(* Logix 5000 project; controller Example_PLC vendor 1 type 14 code 77 rev 19.11; software revision 19.01; part 2 of 6 *)
(* tags used below, declared in another part *)
   Attribute_Number : INT;   // Attribute Number (see help for options)
   ENABLE : BOOL;
   from : BOOL;
(* AKD_Get_Attribute, continued *)

ROUTINE Prescan   (* ladder *)
// Prescan
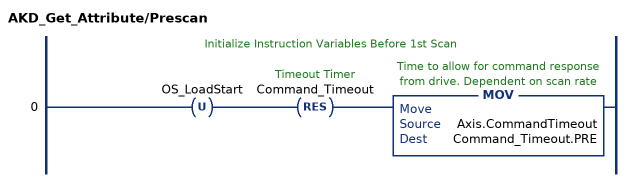
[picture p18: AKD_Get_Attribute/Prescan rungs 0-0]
   // Initialize Instruction Variables Before 1st Scan
   0: OTU(OS_LoadStart)RES(Command_Timeout)MOV(Axis.CommandTimeout,Command_Timeout.PRE);
END_ROUTINE
END_ADD_ON_INSTRUCTION

ADD_ON_INSTRUCTION AKD_Get_Parameter   (* revision 2.0, ExecutePrescan, ExecuteEnableInFalse *)
// Get Drive Parameter
VAR_OUTPUT
   DN : BOOL; {access Read Only, visible}   // Command Successful
   ER : BOOL; {access Read Only, visible}   // Error
END_VAR
VAR_IN_OUT
   Axis : AKD_Axis; {required}
END_VAR
VAR_INPUT
   Parameter_Number : INT; {visible}   // See help (F1) for parameter list.
END_VAR
VAR_OUTPUT
   Parameter_Value : DINT; {access Read Only, required}   // Parameter Value
END_VAR
VAR
   Command_Timeout : TIMER := (PRE := 2000);   // Timeout Timer
   Command_Message_Type : SINT;   // Command Message Type
   Command_Axis_Number : SINT;   // Command Axis Number
   Step : SINT;
   Command_Bytes : SINT[8];
   OS_LoadStart : BOOL;
   Temp_Bytes : SINT[2];   // Temporary Bytes to Split into Command Bytes
END_VAR

ROUTINE EnableInFalse   (* ladder *)
// EnableIn_False
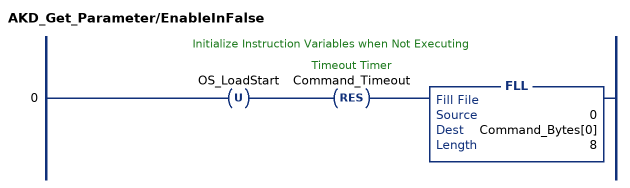
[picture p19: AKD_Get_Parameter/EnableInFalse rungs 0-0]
   // Initialize Instruction Variables when Not Executing
   0: OTU(OS_LoadStart)RES(Command_Timeout)FLL(0,Command_Bytes[0],8);
END_ROUTINE

ROUTINE Logic   (* ladder *)
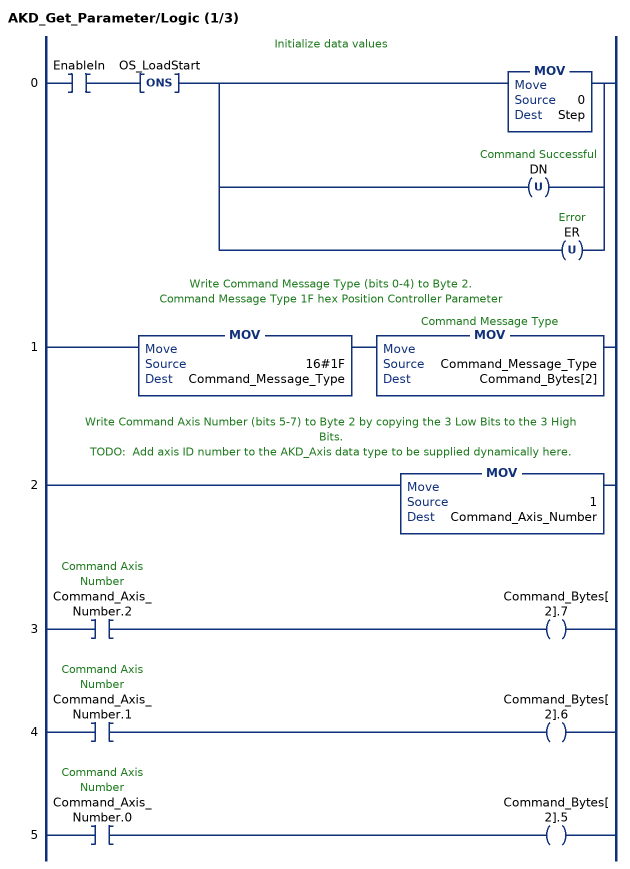
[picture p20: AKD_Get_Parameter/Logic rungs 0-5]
   // Initialize data values
   0: XIC(EnableIn)ONS(OS_LoadStart)[MOV(0,Step) ,OTU(DN) ,OTU(ER) ];
   // Write Command Message Type (bits 0-4) to Byte 2.
   // Command Message Type 1F hex Position Controller Parameter
   1: MOV(16#1F,Command_Message_Type)MOV(Command_Message_Type,Command_Bytes[2]);
   // Write Command Axis Number (bits 5-7) to Byte 2 by copying the 3 Low Bits to the 3 High Bits.
   // TODO:  Add axis ID number to the AKD_Axis data type to be supplied dynamically here.
   2: MOV(1,Command_Axis_Number);
   3: XIC(Command_Axis_Number.2)OTE(Command_Bytes[2].7);
   4: XIC(Command_Axis_Number.1)OTE(Command_Bytes[2].6);
   5: XIC(Command_Axis_Number.0)OTE(Command_Bytes[2].5);
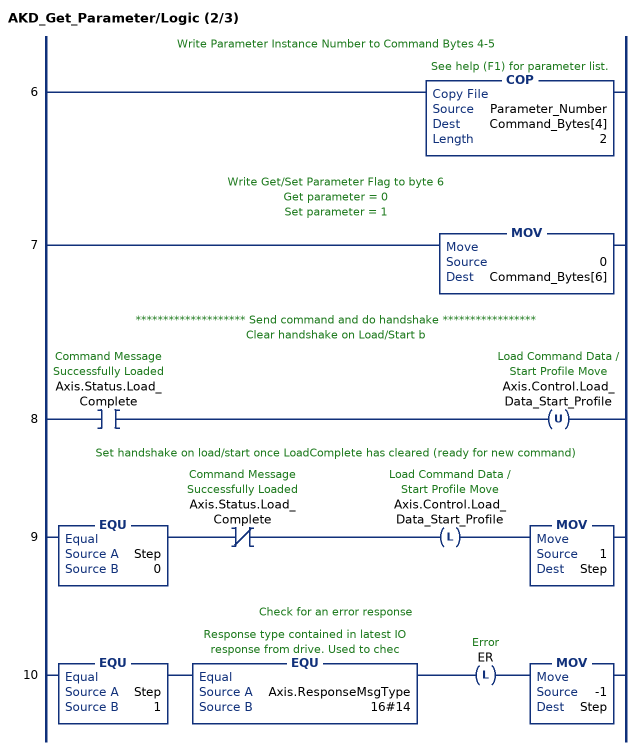
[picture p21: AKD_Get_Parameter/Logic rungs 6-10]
   // Write Parameter Instance Number to Command Bytes 4-5
   6: COP(Parameter_Number,Command_Bytes[4],2);
   // Write Get/Set Parameter Flag to byte 6
   // Get parameter = 0
   // Set parameter = 1
   7: MOV(0,Command_Bytes[6]);
   // ******************** Send command and do handshake *****************
   // Clear handshake on Load/Start b
   8: XIC(Axis.Status.Load_Complete)OTU(Axis.Control.Load_Data_Start_Profile);
   // Set handshake on load/start once LoadComplete has cleared (ready for new command)
   9: EQU(Step,0)XIO(Axis.Status.Load_Complete)OTL(Axis.Control.Load_Data_Start_Profile)MOV(1,Step);
   // Check for an error response
   10: EQU(Step,1)EQU(Axis.ResponseMsgType,16#14)OTL(ER)MOV(-1,Step);
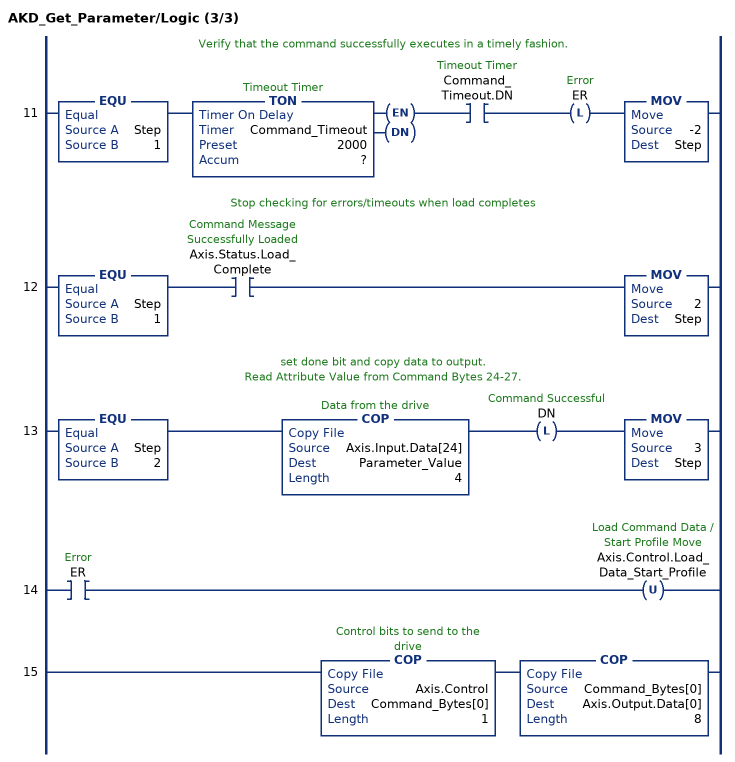
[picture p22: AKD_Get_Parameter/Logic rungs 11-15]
   // Verify that the command successfully executes in a timely fashion.
   11: EQU(Step,1)TON(Command_Timeout,?,?)XIC(Command_Timeout.DN)OTL(ER)MOV(-2,Step);
   // Stop checking for errors/timeouts when load completes
   12: EQU(Step,1)XIC(Axis.Status.Load_Complete)MOV(2,Step);
   // set done bit and copy data to output.
   // Read Attribute Value from Command Bytes 24-27.
   13: EQU(Step,2)COP(Axis.Input.Data[24],Parameter_Value,4)OTL(DN)MOV(3,Step);
   14: XIC(ER)OTU(Axis.Control.Load_Data_Start_Profile);
   15: COP(Axis.Control,Command_Bytes[0],1)COP(Command_Bytes[0],Axis.Output.Data[0],8);
END_ROUTINE

ROUTINE Prescan   (* ladder *)
// Prescan
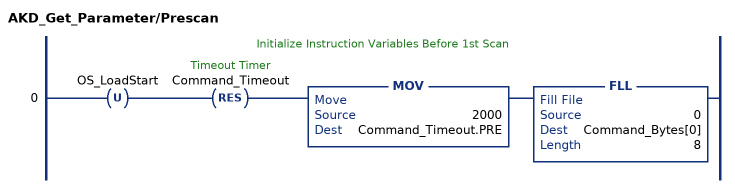
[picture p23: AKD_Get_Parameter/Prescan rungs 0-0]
   // Initialize Instruction Variables Before 1st Scan
   0: OTU(OS_LoadStart)RES(Command_Timeout)MOV(2000,Command_Timeout.PRE)FLL(0,Command_Bytes[0],8);
END_ROUTINE
END_ADD_ON_INSTRUCTION

ADD_ON_INSTRUCTION AKD_Home   (* revision 4.0, ExecutePrescan, ExecuteEnableInFalse *)
// Home Axis
// Revision note:
// added timeout
// removed race with SetAttribute.dn bit
VAR_OUTPUT
   DN : BOOL; {access Read Only, visible}   // Command Successfully Initiated
   ER : BOOL; {access Read Only, visible}   // Error
   IP : BOOL; {access Read Only, visible}   // Command in Process
   PC : BOOL; {access Read Only, visible}   // Command Process Complete
END_VAR
VAR_IN_OUT
   Axis : AKD_Axis; {required}
END_VAR
VAR_INPUT
   TimeOut_mS : DINT; {required}
END_VAR
VAR
   Step : SINT;
   Set_Attribute : AKD_Set_Attribute;
   Value : DINT;
   StartONS : BOOL;
   TimeOut : TIMER := (PRE := 5000); {access None}
END_VAR

ROUTINE EnableInFalse   (* ladder *)
// EnableIn_False
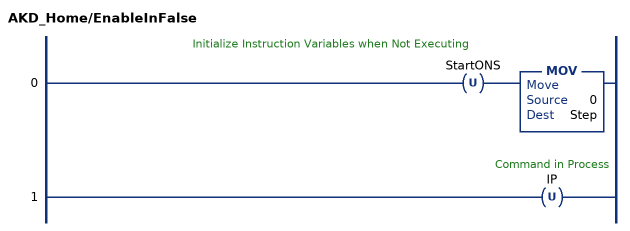
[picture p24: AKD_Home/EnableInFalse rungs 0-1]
   // Initialize Instruction Variables when Not Executing
   0: OTU(StartONS)MOV(0,Step);
   1: OTU(IP);
END_ROUTINE

ROUTINE Logic   (* ladder *)
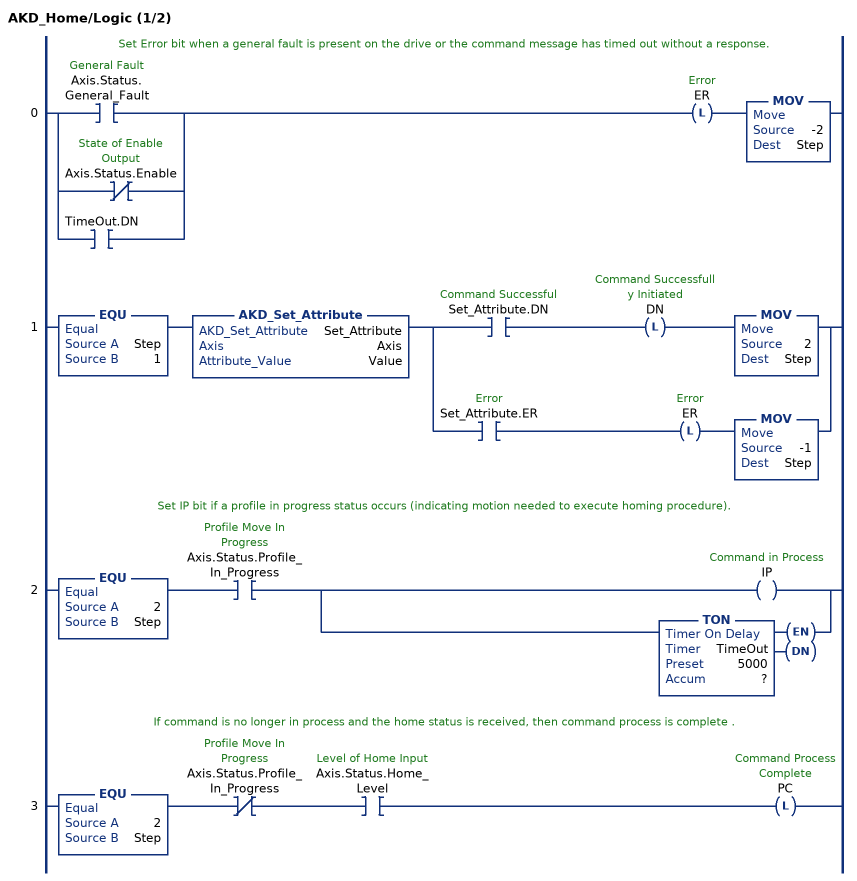
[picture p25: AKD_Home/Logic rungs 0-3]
   // Set Error bit when a general fault is present on the drive or the command message has timed out without a response.
   0: [XIC(Axis.Status.General_Fault) ,XIO(Axis.Status.Enable) ,XIC(TimeOut.DN) ]OTL(ER)MOV(-2,Step);
   1: EQU(Step,1)AKD_Set_Attribute(Set_Attribute,Axis,Value)[XIC(Set_Attribute.DN) OTL(DN) MOV(2,Step) ,XIC(Set_Attribute.ER) OTL(ER) MOV(-1,Step) ];
   // Set IP bit if a profile in progress status occurs (indicating motion needed to execute homing procedure).
   2: EQU(2,Step)XIC(Axis.Status.Profile_In_Progress)[OTE(IP) ,TON(TimeOut,?,?) ];
   // If command is no longer in process and the home status is received, then command process is complete .
   3: EQU(2,Step)XIO(Axis.Status.Profile_In_Progress)XIC(Axis.Status.Home_Level)OTL(PC);
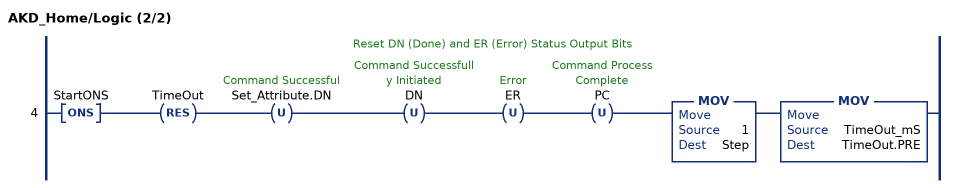
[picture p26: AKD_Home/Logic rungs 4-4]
   // Reset DN (Done) and ER (Error) Status Output Bits
   4: ONS(StartONS)RES(TimeOut)OTU(Set_Attribute.DN)OTU(DN)OTU(ER)OTU(PC)MOV(1,Step)MOV(TimeOut_mS,TimeOut.PRE);
END_ROUTINE

ROUTINE Prescan   (* ladder *)
// Prescan
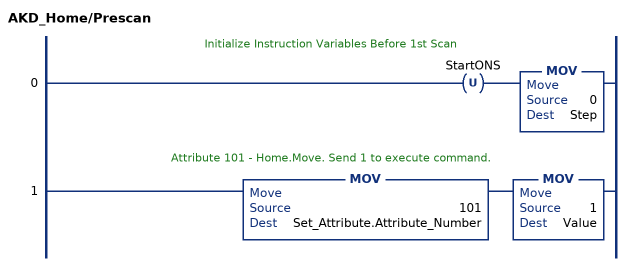
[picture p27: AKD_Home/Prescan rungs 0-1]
   // Initialize Instruction Variables Before 1st Scan
   0: OTU(StartONS)MOV(0,Step);
   // Attribute 101 - Home.Move. Send 1 to execute command.
   1: MOV(101,Set_Attribute.Attribute_Number)MOV(1,Value);
END_ROUTINE
END_ADD_ON_INSTRUCTION

ADD_ON_INSTRUCTION AKD_Jog   (* revision 2.3, ExecutePrescan, ExecuteEnableInFalse *)
// Motion Axis Jog
// Revision note:
// Remove unused IP output
VAR_IN_OUT
   Axis : AKD_Axis; {required}
END_VAR
VAR_INPUT
   Accel : DINT; {required}   // Acceleration
   Decel : DINT; {required}   // Deceleration
   Direction : BOOL; {required}   // 1=Forward/Positive, 0=Reverse/Negative
   Speed : DINT; {required}   // Jog Speed
END_VAR
VAR_OUTPUT
   DN : BOOL; {access Read Only, visible}   // Command Successfully Initiated
   ER : BOOL; {access Read Only, visible}   // Error
END_VAR
VAR
   Accel_Internal : DINT;   // Scaled Accel Value for Drive
   Set_Enable : AKD_Enable;
   Set_Accel : AKD_Set_Accel;
   Set_Decel : AKD_Set_Decel;
   Set_Velocity : AKD_Set_Velocity;
   Step : SINT;   // Sequence Step Number
   Command_Axis_Number : SINT;
   Response_Axis_Number : SINT;
   OS_Start_Sequence : BOOL;
   Command_Bytes : SINT[64];
   ErrorData : SINT[8];
   Command_Timeout : TIMER := (PRE := 100);
END_VAR

ROUTINE EnableInFalse   (* ladder *)
// EnableIn_False
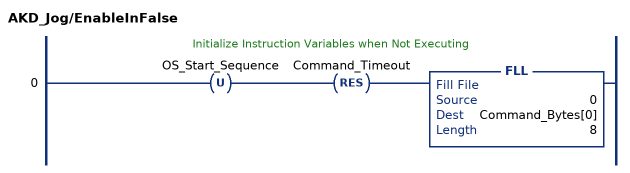
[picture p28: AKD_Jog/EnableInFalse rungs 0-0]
   // Initialize Instruction Variables when Not Executing
   0: OTU(OS_Start_Sequence)RES(Command_Timeout)FLL(0,Command_Bytes[0],8);
END_ROUTINE

ROUTINE Logic   (* ladder *)
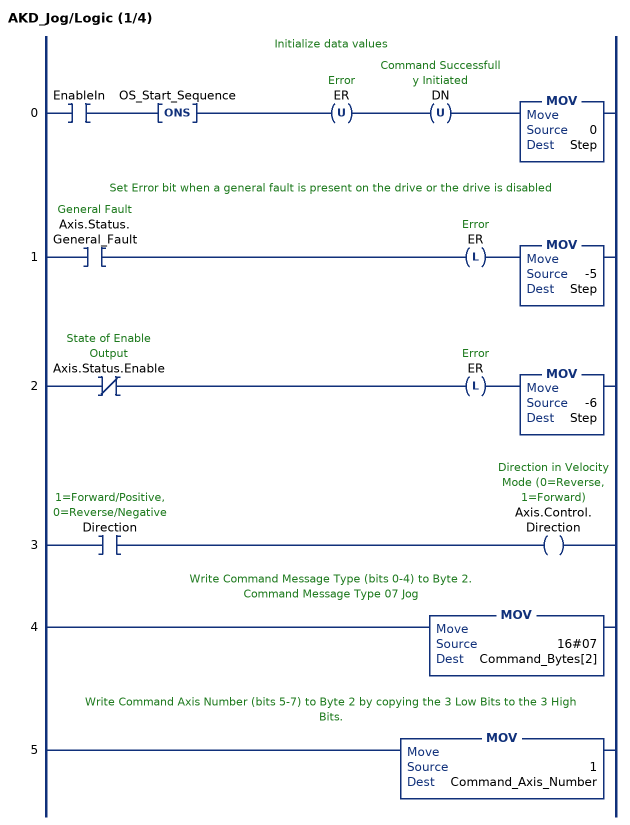
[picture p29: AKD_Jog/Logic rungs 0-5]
   // Initialize data values
   0: XIC(EnableIn)ONS(OS_Start_Sequence)OTU(ER)OTU(DN)MOV(0,Step);
   // Set Error bit when a general fault is present on the drive or the drive is disabled
   1: XIC(Axis.Status.General_Fault)OTL(ER)MOV(-5,Step);
   2: XIO(Axis.Status.Enable)OTL(ER)MOV(-6,Step);
   3: XIC(Direction)OTE(Axis.Control.Direction);
   // Write Command Message Type (bits 0-4) to Byte 2.
   // Command Message Type 07 Jog
   4: MOV(16#07,Command_Bytes[2]);
   // Write Command Axis Number (bits 5-7) to Byte 2 by copying the 3 Low Bits to the 3 High Bits.
   5: MOV(1,Command_Axis_Number);
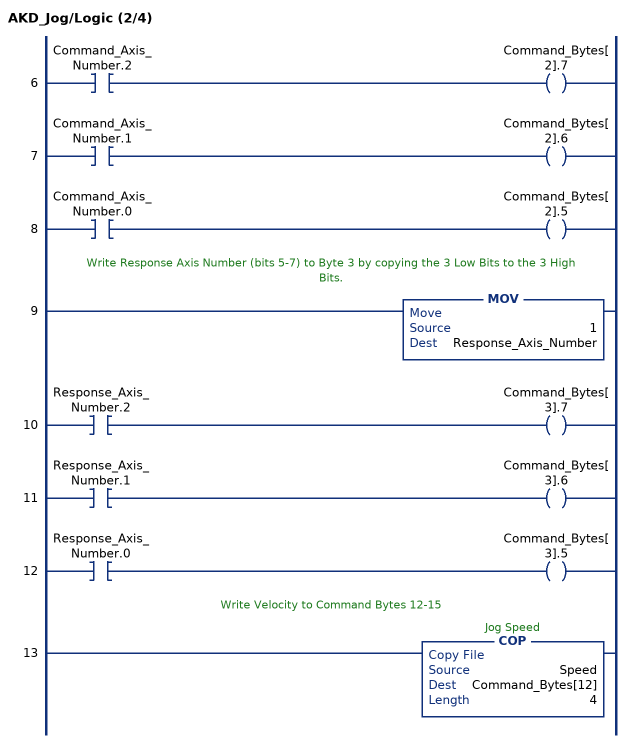
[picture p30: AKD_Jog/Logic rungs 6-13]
   6: XIC(Command_Axis_Number.2)OTE(Command_Bytes[2].7);
   7: XIC(Command_Axis_Number.1)OTE(Command_Bytes[2].6);
   8: XIC(Command_Axis_Number.0)OTE(Command_Bytes[2].5);
   // Write Response Axis Number (bits 5-7) to Byte 3 by copying the 3 Low Bits to the 3 High Bits.
   9: MOV(1,Response_Axis_Number);
   10: XIC(Response_Axis_Number.2)OTE(Command_Bytes[3].7);
   11: XIC(Response_Axis_Number.1)OTE(Command_Bytes[3].6);
   12: XIC(Response_Axis_Number.0)OTE(Command_Bytes[3].5);
   // Write Velocity to Command Bytes 12-15
   13: COP(Speed,Command_Bytes[12],4);
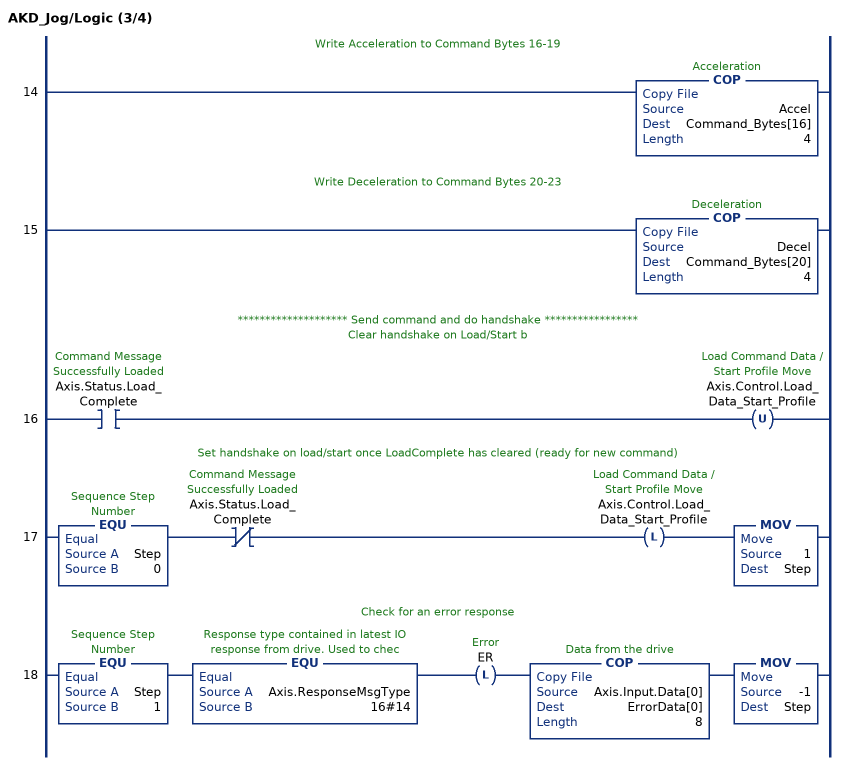
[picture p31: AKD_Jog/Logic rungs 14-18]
   // Write Acceleration to Command Bytes 16-19
   14: COP(Accel,Command_Bytes[16],4);
   // Write Deceleration to Command Bytes 20-23
   15: COP(Decel,Command_Bytes[20],4);
   // ******************** Send command and do handshake *****************
   // Clear handshake on Load/Start b
   16: XIC(Axis.Status.Load_Complete)OTU(Axis.Control.Load_Data_Start_Profile);
   // Set handshake on load/start once LoadComplete has cleared (ready for new command)
   17: EQU(Step,0)XIO(Axis.Status.Load_Complete)OTL(Axis.Control.Load_Data_Start_Profile)MOV(1,Step);
   // Check for an error response
   18: EQU(Step,1)EQU(Axis.ResponseMsgType,16#14)OTL(ER)COP(Axis.Input.Data[0],ErrorData[0],8)MOV(-1,Step);
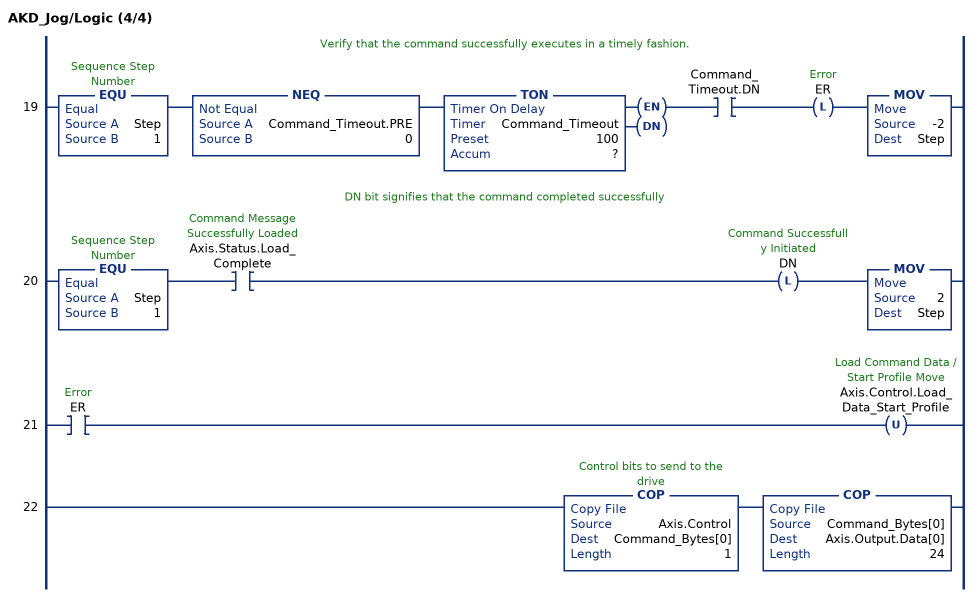
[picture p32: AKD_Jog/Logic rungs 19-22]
   // Verify that the command successfully executes in a timely fashion.
   19: EQU(Step,1)NEQ(Command_Timeout.PRE,0)TON(Command_Timeout,?,?)XIC(Command_Timeout.DN)OTL(ER)MOV(-2,Step);
   // DN bit signifies that the command completed successfully
   20: EQU(Step,1)XIC(Axis.Status.Load_Complete)OTL(DN)MOV(2,Step);
   21: XIC(ER)OTU(Axis.Control.Load_Data_Start_Profile);
   22: COP(Axis.Control,Command_Bytes[0],1)COP(Command_Bytes[0],Axis.Output.Data[0],24);
END_ROUTINE

ROUTINE Prescan   (* ladder *)
// Prescan
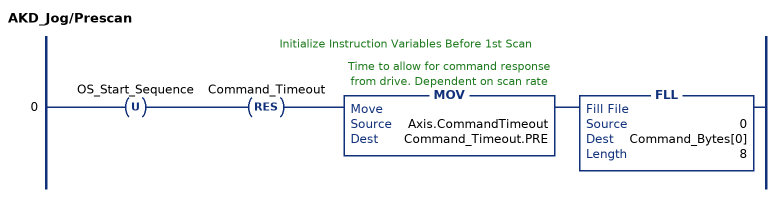
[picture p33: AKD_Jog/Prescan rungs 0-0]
   // Initialize Instruction Variables Before 1st Scan
   0: OTU(OS_Start_Sequence)RES(Command_Timeout)MOV(Axis.CommandTimeout,Command_Timeout.PRE)FLL(0,Command_Bytes[0],8);
END_ROUTINE
END_ADD_ON_INSTRUCTION

ADD_ON_INSTRUCTION AKD_Move   (* revision 3.1, ExecutePrescan, ExecuteEnableInFalse *)
// Motion Axis Move - Position Move
// Revision note:
// Don't error if Command_Timeout preset is 0
VAR_IN_OUT
   Axis : AKD_Axis; {required}
END_VAR
VAR_INPUT
   Move_Type : SINT; {required}   // Move Type (0=Absolute, 1=Incremental)
   Accel : DINT; {required}   // Acceleration
   Decel : DINT; {required}   // Deceleration
   Speed : DINT; {required}   // Move Speed
   Position : DINT; {required}   // Target Position
END_VAR
VAR_OUTPUT
   DN : BOOL; {access Read Only, visible}   // Command Successfully Initiated
   ER : BOOL; {access Read Only, visible}   // Error
   IP : BOOL; {access Read Only, visible}   // Command in Process
   PC : BOOL; {access Read Only, visible}   // Command Process Complete
END_VAR
VAR
   Step : SINT;   // Sequence Step Number
   Command_Axis_Number : SINT;
   Response_Axis_Number : SINT;
   Set_Accel : AKD_Set_Accel;
   Set_Decel : AKD_Set_Decel;
   Set_Velocity : AKD_Set_Velocity;
   OS_Start_Sequence : BOOL;
   Set_Position : AKD_Set_Position;
   Command_Timeout : TIMER := (PRE := 200);
   Command_Bytes : SINT[64];
   ErrorData : SINT[8];
END_VAR

ROUTINE EnableInFalse   (* ladder *)
// EnableIn_False
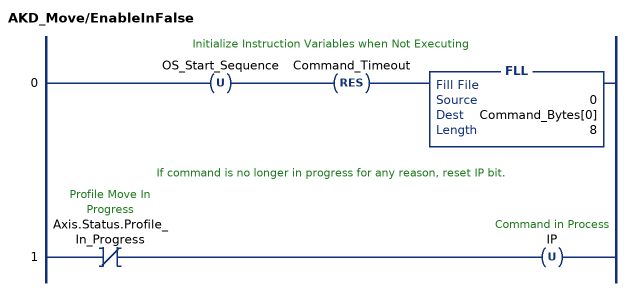
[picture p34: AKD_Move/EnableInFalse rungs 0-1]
   // Initialize Instruction Variables when Not Executing
   0: OTU(OS_Start_Sequence)RES(Command_Timeout)FLL(0,Command_Bytes[0],8);
   // If command is no longer in progress for any reason, reset IP bit.
   1: XIO(Axis.Status.Profile_In_Progress)OTU(IP);
END_ROUTINE

ROUTINE Logic   (* ladder *)
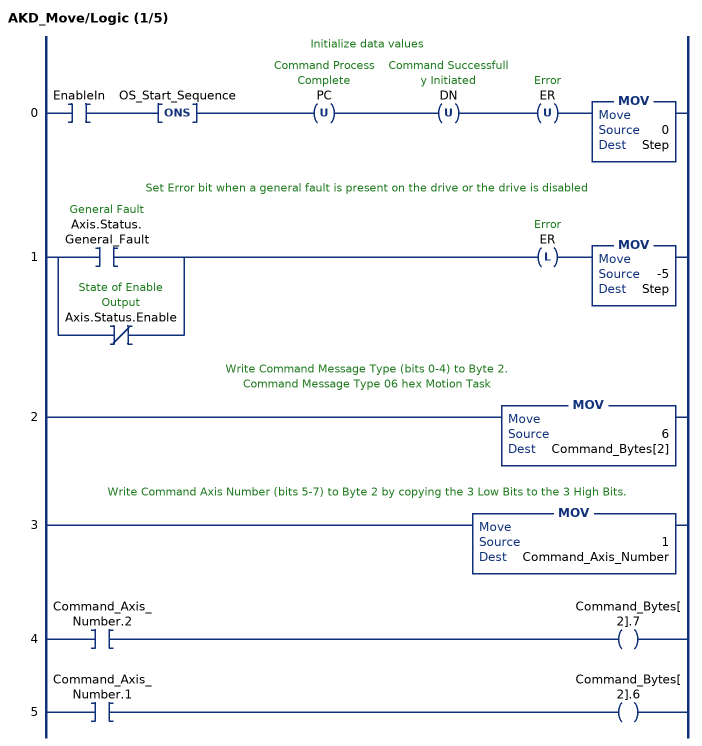
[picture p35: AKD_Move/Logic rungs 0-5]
   // Initialize data values
   0: XIC(EnableIn)ONS(OS_Start_Sequence)OTU(PC)OTU(DN)OTU(ER)MOV(0,Step);
   // Set Error bit when a general fault is present on the drive or the drive is disabled
   1: [XIC(Axis.Status.General_Fault) ,XIO(Axis.Status.Enable) ]OTL(ER)MOV(-5,Step);
   // Write Command Message Type (bits 0-4) to Byte 2.
   // Command Message Type 06 hex Motion Task
   2: MOV(6,Command_Bytes[2]);
   // Write Command Axis Number (bits 5-7) to Byte 2 by copying the 3 Low Bits to the 3 High Bits.
   3: MOV(1,Command_Axis_Number);
   4: XIC(Command_Axis_Number.2)OTE(Command_Bytes[2].7);
   5: XIC(Command_Axis_Number.1)OTE(Command_Bytes[2].6);
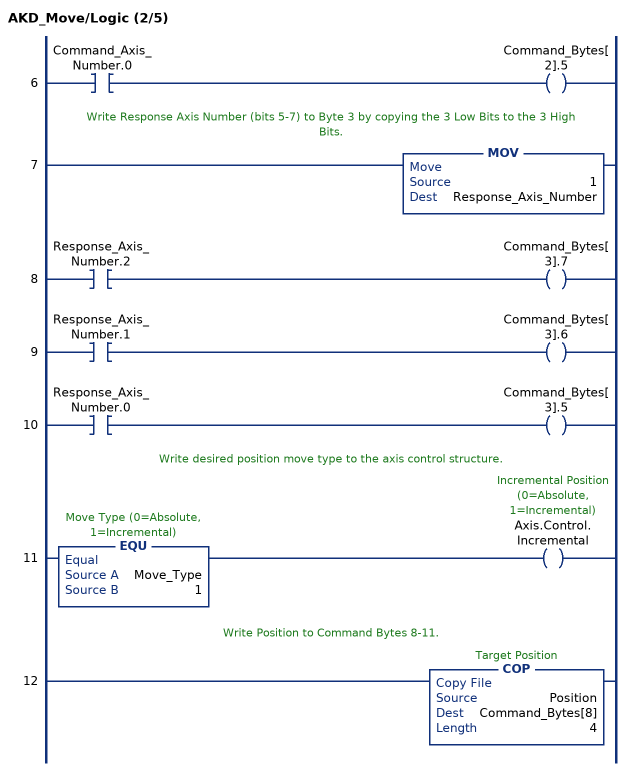
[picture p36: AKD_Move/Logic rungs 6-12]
   6: XIC(Command_Axis_Number.0)OTE(Command_Bytes[2].5);
   // Write Response Axis Number (bits 5-7) to Byte 3 by copying the 3 Low Bits to the 3 High Bits.
   7: MOV(1,Response_Axis_Number);
   8: XIC(Response_Axis_Number.2)OTE(Command_Bytes[3].7);
   9: XIC(Response_Axis_Number.1)OTE(Command_Bytes[3].6);
   10: XIC(Response_Axis_Number.0)OTE(Command_Bytes[3].5);
   // Write desired position move type to the axis control structure.
   11: EQU(Move_Type,1)OTE(Axis.Control.Incremental);
   // Write Position to Command Bytes 8-11.
   12: COP(Position,Command_Bytes[8],4);
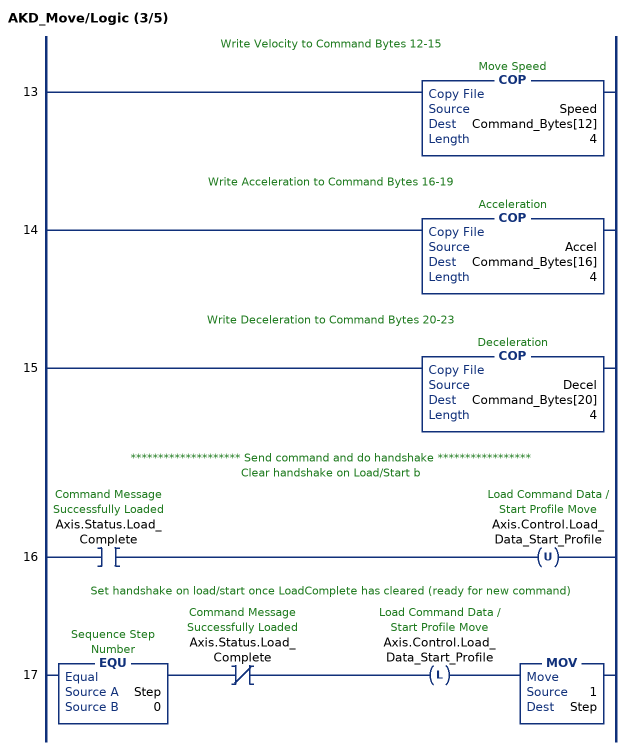
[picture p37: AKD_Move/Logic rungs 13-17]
   // Write Velocity to Command Bytes 12-15
   13: COP(Speed,Command_Bytes[12],4);
   // Write Acceleration to Command Bytes 16-19
   14: COP(Accel,Command_Bytes[16],4);
   // Write Deceleration to Command Bytes 20-23
   15: COP(Decel,Command_Bytes[20],4);
   // ******************** Send command and do handshake *****************
   // Clear handshake on Load/Start b
   16: XIC(Axis.Status.Load_Complete)OTU(Axis.Control.Load_Data_Start_Profile);
   // Set handshake on load/start once LoadComplete has cleared (ready for new command)
   17: EQU(Step,0)XIO(Axis.Status.Load_Complete)OTL(Axis.Control.Load_Data_Start_Profile)MOV(1,Step);
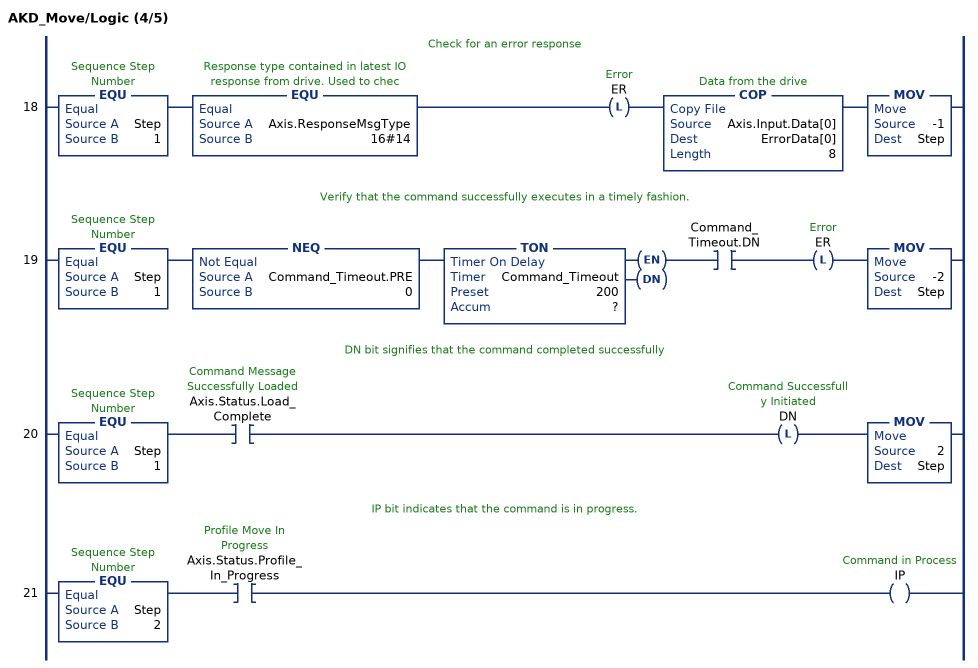
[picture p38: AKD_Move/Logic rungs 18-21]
   // Check for an error response
   18: EQU(Step,1)EQU(Axis.ResponseMsgType,16#14)OTL(ER)COP(Axis.Input.Data[0],ErrorData[0],8)MOV(-1,Step);
   // Verify that the command successfully executes in a timely fashion.
   19: EQU(Step,1)NEQ(Command_Timeout.PRE,0)TON(Command_Timeout,?,?)XIC(Command_Timeout.DN)OTL(ER)MOV(-2,Step);
   // DN bit signifies that the command completed successfully
   20: EQU(Step,1)XIC(Axis.Status.Load_Complete)OTL(DN)MOV(2,Step);
   // IP bit indicates that the command is in progress.
   21: EQU(Step,2)XIC(Axis.Status.Profile_In_Progress)OTE(IP);
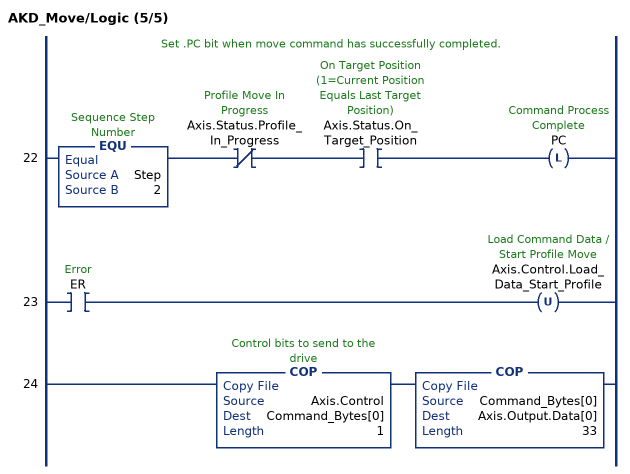
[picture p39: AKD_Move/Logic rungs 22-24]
   // Set .PC bit when move command has successfully completed.
   22: EQU(Step,2)XIO(Axis.Status.Profile_In_Progress)XIC(Axis.Status.On_Target_Position)OTL(PC);
   23: XIC(ER)OTU(Axis.Control.Load_Data_Start_Profile);
   24: COP(Axis.Control,Command_Bytes[0],1)COP(Command_Bytes[0],Axis.Output.Data[0],33);
END_ROUTINE
